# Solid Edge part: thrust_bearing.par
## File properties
Title: Thrust bearing
Author: Abhinav Rai
Template: Normal.par
Last saved by: Cadcim
Revision: 9
Application: Solid Edge
Material: aluminum
Accuracy: 0.99
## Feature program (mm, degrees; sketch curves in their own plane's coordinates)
sketch for "unnamed RevolvedProtrusion 1" plane through (0, 0, 0) normal (0, -1, 0) x-axis (1, 0, 0)
  line (47.625, 16.8036) -> (66.929, 16.8036)
  line (66.929, 16.8036) -> (73.025, 10.7076)
  line (73.025, 10.7076) -> (73.025, -12.0254)
  line (73.025, -12.0254) -> (66.929, -18.1214)
  line (66.929, -18.1214) -> (47.625, -18.1214)
  line (47.625, -18.1214) -> (47.625, -7.1994)
  line (61.5714, -7.1994) -> (47.625, -7.1994)
  line (61.5714, 5.8816) -> (61.5714, -7.1994)
  line (47.625, 5.8816) -> (61.5714, 5.8816)
  line (47.625, 5.8816) -> (47.625, 16.8036)
revolve "unnamed RevolvedProtrusion 1" add finite 360 deg
sketch for "unnamed RevolvedProtrusion 2" plane through (0, 0, 0) normal (1, 0, 0) x-axis (0, 1, 0)
  line (69.977, 13.7556) -> (73.0652, 13.7556)
  line (73.0652, 13.7556) -> (74.6125, 12.2083)
  line (74.6125, 12.2083) -> (74.6125, -13.4669)
  line (74.6125, -13.4669) -> (73.006, -15.0734)
  line (73.006, -15.0734) -> (69.977, -15.0734)
revolve "unnamed RevolvedProtrusion 2" add full turn 360 deg
sketch for "unnamed RevolvedProtrusion 3" plane through (0, 0, 0) normal (0, -1, 0) x-axis (1, 0, 0)
revolve "unnamed RevolvedProtrusion 3" add full turn 360 deg about sketch line (-54.9674, 10.1232) -> (-54.9674, -18.1214)
pattern "unnamed Pattern 1" of "unnamed RevolvedProtrusion 3"
pattern "unnamed Pattern 2"
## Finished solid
Body 1: solid body, 39 faces, 39 edges, 25 vertices.
  Faces by surface: torus 25, plane 6, cone 4, cylinder 4
  Edges by curve: circle 39
Bounding box of the edges (mm; curved faces can reach further): 149.225 x 149.225 x 34.925, from (-74.6125, -74.6125, -18.1214) to (74.6125, 74.6125, 16.8036).
Cylindrical faces by radius (mm): R47.625 x2, R61.5714 x1, R74.6125 x1
Conical faces (half-angle, radius in mm at the cone's reference point): 45 deg R66.929 x1, 45 deg R73.025 x1, 45 deg R73.0652 x1, 45 deg R74.6125 x1
Toroidal faces (ring radius, tube radius in mm): R-0.1023 r6.604 x25
Planar faces by outward normal: +z 3, -z 3
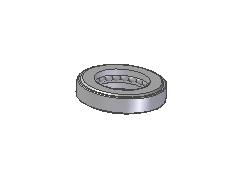
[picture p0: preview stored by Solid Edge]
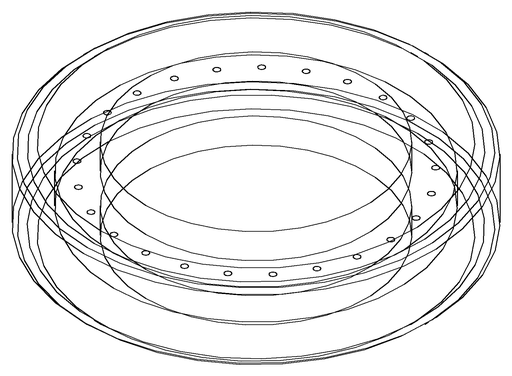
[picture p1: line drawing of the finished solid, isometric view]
